// TIA Portal project "sample_modbus_test" (V15)

(* hardware
DEVICE "S71500/ET200MP station_1"  S7-1500 station
   slot 0: "导轨_0"  Rack  6ES7 590-1***0-0AA0
   slot 1: "PLC_1"  CPU 1511-1 PN  6ES7 511-1AK01-0AB0  V1.8
      slot 3: "CPU 显示_1"  6ES7591-1AA00-0AA0
*)

// ===== PLC "PLC_1"  CPU 1511-1 PN =====

VAR_GLOBAL   // PLC tag table "默认变量表"
   "Tag_1" AT %M10.0 : Bool;
   "Tag_2" AT %M10.1 : Bool;
   "Tag_3" AT %M10.2 : Bool;
   "Tag_4" AT %M10.3 : Bool;
   "Tag_5" AT %MW11 : Word;
   "Tag_6" AT %MB100 : Byte;
   "Tag_7" AT %MW100 : Word;
   "Tag_8" AT %MW102 : Word;
   "Clock_Byte" AT %MB0 : Byte;
   "Clock_10Hz" AT %M0.0 : Bool;
   "Clock_5Hz" AT %M0.1 : Bool;
   "Clock_2.5Hz" AT %M0.2 : Bool;
   "Clock_2Hz" AT %M0.3 : Bool;
   "Clock_1.25Hz" AT %M0.4 : Bool;
   "Clock_1Hz" AT %M0.5 : Bool;
   "Clock_0.625Hz" AT %M0.6 : Bool;
   "Clock_0.5Hz" AT %M0.7 : Bool;
   "Tag_9" AT %M10.5 : Bool;
   "Tag_10" AT %MB200 : Char;
   "Tag_11" AT %M10.6 : Bool;
   "Tag_12" AT %M10.7 : Bool;
END_VAR

VAR_GLOBAL   // PLC tag table "MV_ID_TAGS"
   "Trigger Enable" AT %M100.0 : Bool;
   "Trigger" AT %M100.1 : Bool;
   "Results Ack" AT %M100.2 : Bool;
   "Clear Error" AT %M101.7 : Bool;
   "Trigger Ready" AT %M102.0 : Bool;
   "Trigger Ack" AT %M102.1 : Bool;
   "Acquiring" AT %M102.2 : Bool;
   "Decoding" AT %M102.3 : Bool;
   "Results OK" AT %M103.0 : Bool;
   "Results NG" AT %M103.1 : Bool;
   "General Fault" AT %M103.7 : Bool;
END_VAR

DATA_BLOCK "MV_ID_REG"   // DB2
{ S7_Optimized_Access := 'FALSE' }
VERSION : 0.1
   VAR
      Control : Word;
      Status : Word;
      Result : Struct
         "Result Length" : Word;
         "Result Data" : Array[0..199] of Char;
      END_STRUCT;
   END_VAR
BEGIN
END_DATA_BLOCK

DATA_BLOCK "MV_MB_TCON"   // DB3
{ S7_Optimized_Access := 'TRUE' }
VERSION : 0.1
   VAR
      MV_MB_Server : TCON_IP_v4;
   END_VAR
BEGIN
   MV_MB_Server.InterfaceId := 64;
   MV_MB_Server.LocalPort := 502;
   MV_MB_Server.ID := 16#1;
END_DATA_BLOCK

DATA_BLOCK "MV_ID_RESULT"   // DB4
{ S7_Optimized_Access := 'FALSE' }
VERSION : 0.1
   VAR
      result : Array[0..199] of Char;
   END_VAR
BEGIN
END_DATA_BLOCK

ORGANIZATION_BLOCK "Main"   // OB1, LAD, ProgramCycle
TITLE = "Main Program Sweep (Cycle)"
{ S7_Optimized_Access := 'TRUE' }
VERSION : 0.1
   VAR_INPUT
      Initial_Call : Bool;   // Initial call of this OB
      Remanence : Bool;   // =True, if remanent data are available
   END_VAR
   VAR_TEMP   // added for the SCL form of the ladder/FBD networks
      _w1 : Bool;
      _w2 : Bool;
   END_VAR
BEGIN

REGION Network 1: Modbus TCP Server
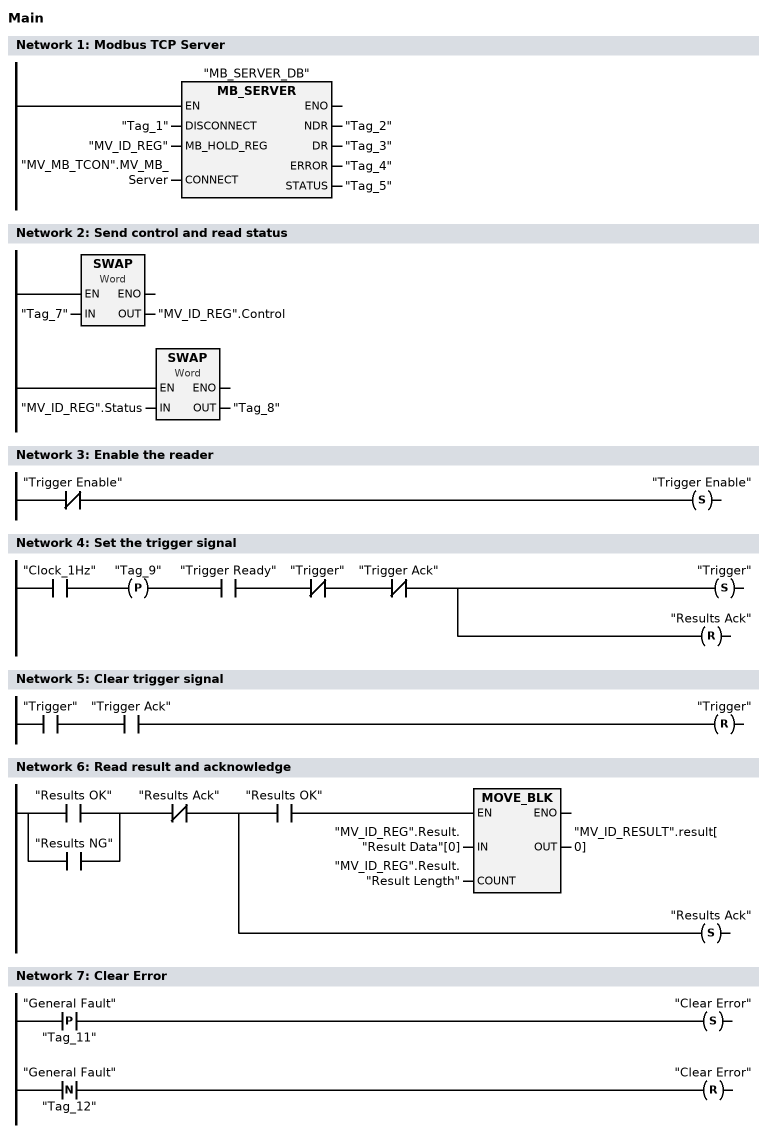
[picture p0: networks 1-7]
   "MB_SERVER_DB"(DISCONNECT := "Tag_1",   // MB_SERVER
                  MB_HOLD_REG := "MV_ID_REG",
                  CONNECT := "MV_MB_TCON".MV_MB_Server,
                  NDR => "Tag_2",
                  DR => "Tag_3",
                  ERROR => "Tag_4",
                  STATUS => "Tag_5");
END_REGION

REGION Network 2: Send control and read status
   "MV_ID_REG".Control := SWAP("Tag_7");
   "Tag_8" := SWAP("MV_ID_REG".Status);
END_REGION

REGION Network 3: Enable the reader
   RUNG wire#powerrail
      I_Contact( "Trigger Enable" )
      S_Coil( "Trigger Enable" )
   END_RUNG
   // the same network as SCL:
   IF NOT "Trigger Enable" THEN "Trigger Enable" := TRUE; END_IF;
END_REGION

REGION Network 4: Set the trigger signal
   RUNG wire#powerrail
      Contact( "Clock_1Hz" )
      P_Trig( "Tag_9" )
      Contact( "Trigger Ready" )
      I_Contact( "Trigger" )
      I_Contact( "Trigger Ack" )
      wire#w1
      S_Coil( "Trigger" )
   END_RUNG
   RUNG wire#w1
      R_Coil( "Results Ack" )
   END_RUNG
   // the same network as SCL:
   #_w1 := "Clock_1Hz" AND NOT "Tag_9";   // rising edge
   "Tag_9" := "Clock_1Hz";
   #_w2 := #_w1 AND "Trigger Ready" AND NOT "Trigger" AND NOT "Trigger Ack";
   IF #_w2 THEN
       "Trigger" := TRUE;
       "Results Ack" := FALSE;
   END_IF;
END_REGION

REGION Network 5: Clear trigger signal
   RUNG wire#powerrail
      Contact( "Trigger" )
      Contact( "Trigger Ack" )
      R_Coil( "Trigger" )
   END_RUNG
   // the same network as SCL:
   IF "Trigger" AND "Trigger Ack" THEN "Trigger" := FALSE; END_IF;
END_REGION

REGION Network 6: Read result and acknowledge
   #_w1 := ("Results OK" OR "Results NG") AND NOT "Results Ack";
   IF #_w1 AND "Results OK" THEN
       MOVE_BLK(IN := "MV_ID_REG".Result."Result Data"[0],
                COUNT := "MV_ID_REG".Result."Result Length",
                OUT => "MV_ID_RESULT".result[0]);
   END_IF;
   IF #_w1 THEN "Results Ack" := TRUE; END_IF;
END_REGION

REGION Network 7: Clear Error
   RUNG wire#powerrail
      P_Contact(operand := "General Fault", bit := "Tag_11")
      S_Coil( "Clear Error" )
   END_RUNG
   RUNG wire#powerrail
      N_Contact(operand := "General Fault", bit := "Tag_12")
      R_Coil( "Clear Error" )
   END_RUNG
   // the same network as SCL:
   #_w1 := "General Fault" AND NOT "Tag_11";   // rising edge of "General Fault"
   "Tag_11" := "General Fault";
   IF #_w1 THEN "Clear Error" := TRUE; END_IF;
   #_w2 := NOT "General Fault" AND "Tag_12";   // falling edge of "General Fault"
   "Tag_12" := "General Fault";
   IF #_w2 THEN "Clear Error" := FALSE; END_IF;
END_REGION
END_ORGANIZATION_BLOCK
